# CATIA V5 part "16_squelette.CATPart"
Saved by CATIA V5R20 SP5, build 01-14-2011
Part number: 16_squelette
Publications: "Point.1", "Point.3", "Droite.2", "hauteur_max_container", "diametre_max_container", "Droite.3", "Point.9", "Droite.4", "Plan.18", "Point.20"
Bounding box of the stored display mesh (mm): x 0 to 0, y -107.638 to 140.362, z -190 to 190
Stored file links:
  C:\Documents and Settings\anizard\Bureau\13\16_squelette.CATPart
  C:\Documents and Settings\anizard\Bureau\13\anizard.CATProduct
  C:\Documents and Settings\anizard\Bureau\13\32_squelette.CATPart
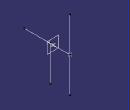
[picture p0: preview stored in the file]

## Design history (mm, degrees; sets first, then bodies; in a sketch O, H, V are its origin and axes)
Parameters
  hauteur_max_container = 190 mm
  diametre_max_container = 194 mm
External parameters (linked from other documents)
  External.diametre = 156 mm
Set1
  Line1: linked copy from another document
  Point1: linked copy from another document
  Point2: linked copy from another document
  Plane1: linked copy from another document
  Point3: linked copy from another document
  Point4: linked copy from another document
Body1 (main body)
  Point5: type OnCurve, Support Line1, RefPoint Point4, Length 17
  Point6: type OnCurve, Support Line1, RefPoint Point5, Length 90 {= External.diametre  / 2 +12mm}
  Line2: type Normal, RefPoint Point6, RefSkin xy-plane, Start -190 {= -hauteur_max_container}, End 190 {= hauteur_max_container}
  Line3: type Angle, RefPoint Point2, Curve Line1, Support yz-plane, Start 0, End 190 {= hauteur_max_container}, Angle -90
  Point7: (0, 23, 0)
  Line4: type PtPt, FirstPoint Point6, SecondPoint Point5, End 158
  Point8: type OnCurve, Support Line4, RefPoint Point5, Length 3.5
  Plane2: type Normal, Curve Line4, RefPoint Point8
